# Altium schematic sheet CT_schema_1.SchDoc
size 382 x 207 mm
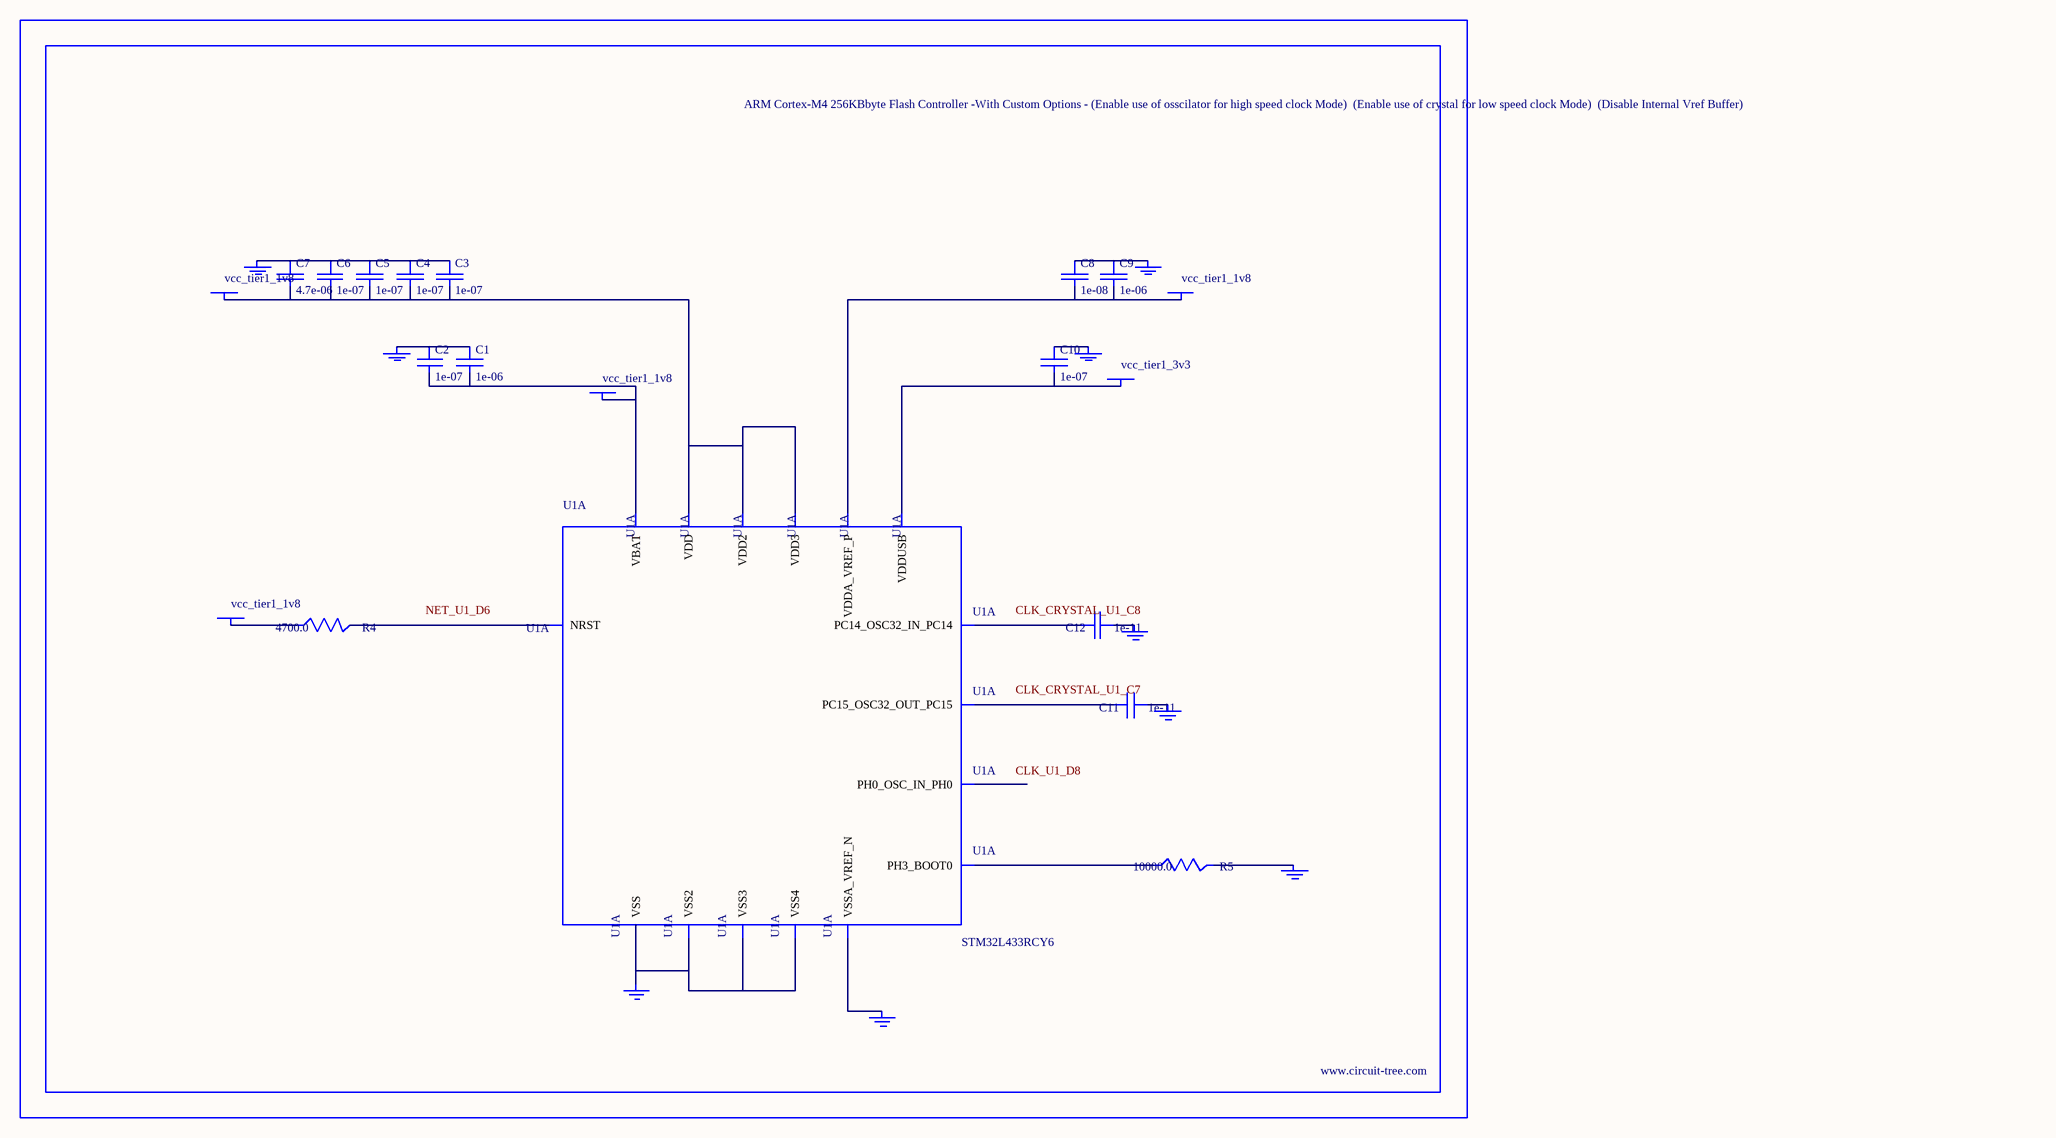
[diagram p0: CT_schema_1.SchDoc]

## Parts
BORDER0  (no value)
C1  1e-06  [C0603]
C2  1e-07  [C0603]
C3  1e-07  [C0603]
C4  1e-07  [C0603]
C5  1e-07  [C0603]
C6  1e-07  [C0603]
C7  4.7e-06  [C0603]
C8  1e-08  [C0603]
C9  1e-06  [C0603]
C10  1e-07  [C0603]
C11  1e-11  [C0402]
C12  1e-11  [C0402]
GND_INSTANCE_0_0  (no value)
GND_INSTANCE_0_1  (no value)
GND_INSTANCE_0_2  (no value)
GND_INSTANCE_0_3  (no value)
GND_INSTANCE_0_4  (no value)
GND_INSTANCE_0_5  (no value)
GND_INSTANCE_0_6  (no value)
GND_INSTANCE_0_7  (no value)
GND_INSTANCE_0_8  (no value)
POWER_INSTANCE_0_0  vcc_tier1_1v8
POWER_INSTANCE_0_1  vcc_tier1_1v8
POWER_INSTANCE_0_2  vcc_tier1_1v8
POWER_INSTANCE_0_3  vcc_tier1_3v3
POWER_INSTANCE_0_4  vcc_tier1_1v8
R4  4700.0  [R0603]
R5  10000.0  [R0603]
U1  STM32L433RCY6  [WLCSP64]  (part A of 8)

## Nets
NetC1_1: C1.1 C2.1 GND_INSTANCE_0_0.0(GND)
NetC1_2: C1.2 C2.2 POWER_INSTANCE_0_0.0(PWR) U1.B7(VBAT)
NetC3_1: C3.1 C4.1 C5.1 C6.1 C7.1 GND_INSTANCE_0_1.0(GND)
NetC3_2: C3.2 C4.2 C5.2 C6.2 C7.2 POWER_INSTANCE_0_1.0(PWR) U1.A8(VDD) U1.H1(VDD2) U1.H7(VDD3)
NetC8_1: C8.1 C9.1 GND_INSTANCE_0_3.0(GND)
NetC8_2: C8.2 C9.2 POWER_INSTANCE_0_2.0(PWR) U1.G8(VDDA_VREF_P)
NetC10_1: C10.1 GND_INSTANCE_0_4.0(GND)
NetC10_2: C10.2 POWER_INSTANCE_0_3.0(PWR) U1.A1(VDDUSB)
NetC11_1: C11.1 GND_INSTANCE_0_5.0(GND)
NetC11_2: C11.2 U1.C7(PC15_OSC32_OUT_PC15)
NetC12_1: C12.1 GND_INSTANCE_0_6.0(GND)
NetC12_2: C12.2 U1.C8(PC14_OSC32_IN_PC14)
NetGND_INSTANCE_0_2_0: GND_INSTANCE_0_2.0(GND) R5.2
NetGND_INSTANCE_0_7_0: GND_INSTANCE_0_7.0(GND) U1.F8(VSSA_VREF_N)
NetGND_INSTANCE_0_8_0: GND_INSTANCE_0_8.0(GND) U1.A7(VSS) U1.B1(VSS2) U1.H2(VSS3) U1.H8(VSS4)
NetPOWER_INSTANCE_0_4_0: POWER_INSTANCE_0_4.0(PWR) R4.1
NetR4_2: R4.2 U1.D6(NRST)
NetR5_1: R5.1 U1.C5(PH3_BOOT0)

Not connected (* = marked no-connect by the designer): U1 D8(PH0_OSC_IN_PH0)

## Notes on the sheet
- Labels drawn without touching a wire or pin: CLK_CRYSTAL_U1_C7, CLK_CRYSTAL_U1_C8, CLK_U1_D8, NET_U1_D6

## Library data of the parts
BORDER0 = BORDER_PAGE0
C1 C9 = C0603C105K3RACTU
C2-C6 C10 = 06035C104K4Z2A
C7 = GRM188R6YA475KE15D
C8 = 06035C103K4Z2A
C11 C12 = C0402C100K3GACTU
GND_INSTANCE_0_0-GND_INSTANCE_0_8 = GND
POWER_INSTANCE_0_0-POWER_INSTANCE_0_4 = PWR
R4 = RC0603JR-074K7L
R5 = RC0603JR-0710KL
